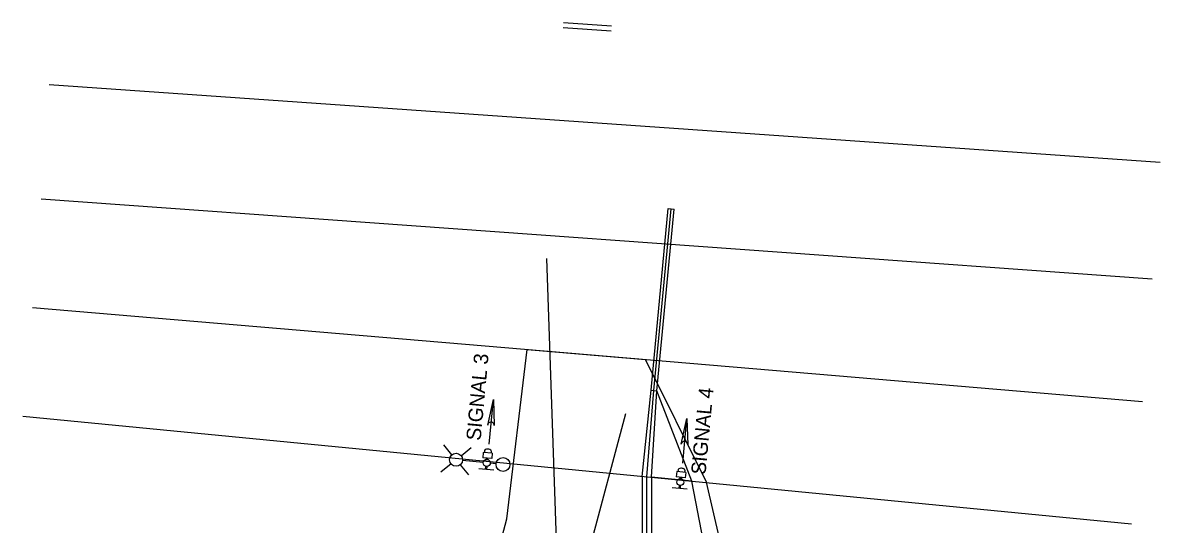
# Model space of a CAD drawing. Extents: x 157201 to 163282, y 424960 to 427200.
# Drawn here: x 157345.2 to 157590.3, y 426719.3 to 426827.4 of the extents above; entities that cross this region are included whole.
import ezdxf

# ---------------------------------------------------------------- set-up
doc = ezdxf.new("R2010")
doc.units = 0
for name, color, linetype in [('Default', 7, 'Continuous'), ('DR_X_Elev_Flow', 7, 'Continuous'), ('DR_X_Text', 7, 'Continuous'), ('PV_X_COP', 7, 'Continuous'), ('RD_X_Gate', 7, 'Continuous'), ('RW_X_CL_100_Distances', 7, 'Continuous'), ('RW_X_CL_100_Stations', 7, 'Continuous'), ('SC_Scratch1', 7, 'Continuous')]:
    doc.layers.add(name, color=color, linetype=linetype)

msp = doc.modelspace()

# ---------------------------------------------------------------- linework, layer by layer
at = {"layer": 'Default'}
for p, q in [((157350.88, 426814.13), (157590.3, 426797.41)), ((157349.15, 426789.45), (157588.53, 426772.21)), ((157347.32, 426766.02), (157586.46, 426745.79)), ((157345.19, 426742.62), (157584.07, 426719.4))]:
    msp.add_line(p, q, dxfattribs=at)
at = {"layer": 'DR_X_Elev_Flow'}
for p, q in [((157480.58, 426748.22), (157484.29, 426787.36)), ((157481.2, 426748.16), (157484.92, 426787.3)), ((157481.83, 426748.1), (157485.54, 426787.24)), ((157484.29, 426787.36), (157485.54, 426787.24)), ((157480.58, 426748.22), (157481.83, 426748.1))]:
    msp.add_line(p, q, dxfattribs=at)
at = {"layer": 'DR_X_Text'}
msp.add_lwpolyline([(157463.89, 426554.35), (157466.5, 426579.29), (157469.22, 426604.16), (157472.03, 426629.01), (157475.65, 426653.85), (157478.07, 426678.99), (157479.6, 426704.21), (157479.68, 426729.54), (157481.2, 426748.16)], dxfattribs=at)
at = {"layer": 'PV_X_COP'}
for p, q in [((157461.67, 426826.44), (157471.98, 426825.72)), ((157472.05, 426826.72), (157461.74, 426827.44))]:
    msp.add_line(p, q, dxfattribs=at)
at = {"layer": 'RD_X_Gate'}
for p, q in [((157478.68, 426729.59), (157480.58, 426748.22)), ((157480.68, 426729.45), (157481.83, 426748.1)), ((157489.37, 426728.6), (157480.67, 426729.45))]:
    msp.add_line(p, q, dxfattribs=at)
for points in [[(157474.64, 426526.21), (157473.17, 426540.97), (157470.15, 426553.45), (157472.65, 426578.43), (157472.95, 426603.63), (157477.4, 426628.25), (157485.18, 426652.56), (157494.07, 426677.03), (157494.42, 426702.58), (157489.37, 426728.6), (157481.83, 426748.1)], [(157478.68, 426729.64), (157478.68, 426729.59), (157478.6, 426704.24), (157477.07, 426679.07), (157474.65, 426653.97), (157471.04, 426629.15)], [(157480.68, 426729.45), (157480.6, 426704.18), (157479.07, 426678.91), (157476.64, 426653.73), (157473.02, 426628.88), (157473.02, 426628.87)]]:
    msp.add_lwpolyline(points, dxfattribs=at)
at = {"layer": 'RW_X_CL_100_Distances'}
msp.add_line((157458.04, 426776.62), (157461.88, 426666.84), dxfattribs=at)
at = {"layer": 'RW_X_CL_100_Stations'}
msp.add_line((157475.1, 426743.11), (157454.94, 426667.74), dxfattribs=at)
at = {"layer": 'SC_Scratch1'}
for p, q in [((157453.88, 426757), (157479.41, 426754.84)), ((157445.38, 426740.71), (157446.6, 426746.24)), ((157445.7, 426736.62), (157446.6, 426746.24)), ((157446.6, 426746.24), (157446.77, 426740.58)), ((157487.09, 426736.57), (157488.31, 426742.11)), ((157487.42, 426732.49), (157488.31, 426742.11)), ((157488.31, 426742.11), (157488.49, 426736.44)), ((157437.68, 426734.29), (157435.9, 426736.46)), ((157439.64, 426734.1), (157441.81, 426735.87)), ((157444.41, 426734.79), (157444.31, 426733.65)), ((157446.24, 426733.47), (157444.31, 426733.65)), ((157446.34, 426734.61), (157444.41, 426734.79)), ((157444.7, 426735.26), (157444.66, 426734.78)), ((157445.13, 426733.31), (157445.15, 426733.57)), ((157445.13, 426733.31), (157445.15, 426733.57)), ((157445.37, 426733.29), (157445.39, 426733.55)), ((157445.37, 426733.29), (157445.39, 426733.55)), ((157446.14, 426735.13), (157446.1, 426734.64)), ((157446.34, 426734.61), (157446.24, 426733.47)), ((157437.48, 426732.33), (157435.31, 426730.55)), ((157439.45, 426732.13), (157441.22, 426729.96)), ((157444.43, 426732.63), (157439.95, 426733.07)), ((157446.67, 426731), (157443.44, 426731.3)), ((157444.93, 426731.16), (157444.99, 426731.82)), ((157445.17, 426731.14), (157445.23, 426731.8)), ((157447.19, 426732.36), (157445.93, 426732.48)), ((157486.42, 426731.12), (157486.38, 426730.64)), ((157486.42, 426731.12), (157486.38, 426730.64)), ((157487.86, 426730.99), (157487.81, 426730.51)), ((157487.86, 426730.99), (157487.81, 426730.51)), ((157486.13, 426730.66), (157486.02, 426729.51)), ((157487.95, 426729.34), (157486.02, 426729.51)), ((157488.06, 426730.48), (157486.13, 426730.66)), ((157486.85, 426729.17), (157486.87, 426729.44)), ((157486.85, 426729.17), (157486.87, 426729.44)), ((157487.08, 426729.15), (157487.11, 426729.41)), ((157487.08, 426729.15), (157487.11, 426729.41)), ((157488.06, 426730.48), (157487.95, 426729.34)), ((157488.38, 426726.87), (157485.16, 426727.16)), ((157486.65, 426727.03), (157486.71, 426727.68)), ((157486.65, 426727.03), (157486.71, 426727.68)), ((157486.89, 426727), (157486.95, 426727.66)), ((157486.89, 426727), (157486.95, 426727.66))]:
    msp.add_line(p, q, dxfattribs=at)
for points in [[(157433.24, 426652.29), (157439.66, 426683.3), (157449.49, 426720.51), (157453.88, 426757)], [(157498.43, 426702.94), (157492.53, 426728.36), (157479.41, 426754.84)]]:
    msp.add_lwpolyline(points, dxfattribs=at)
for centre, radius in [((157438.56, 426733.21), 1.4), ((157445.18, 426732.55), 0.757), ((157448.68, 426732.21), 1.5), ((157486.9, 426728.42), 0.757)]:
    msp.add_circle(centre, radius, dxfattribs=at)
for centre in [(157446.08, 426740.64), (157487.79, 426736.5)]:
    msp.add_arc(centre, 0.702, 354.6781, 174.6781, dxfattribs=at)
for centre in [(157445.42, 426735.19), (157487.14, 426731.06), (157487.14, 426731.06)]:
    msp.add_ellipse(centre, major_axis=(0.718, -0.066), ratio=0.45371, start_param=0, end_param=3.141593, dxfattribs=at)

# ---------------------------------------------------------------- texts
for s, p in [('SIGNAL 3', (157443.85, 426737.25)), ('SIGNAL 4', (157492.3, 426729.9))]:
    msp.add_text(s, height=3.125, rotation=84.6781, dxfattribs=at).set_placement(p)

doc.saveas('drawing.dxf')
